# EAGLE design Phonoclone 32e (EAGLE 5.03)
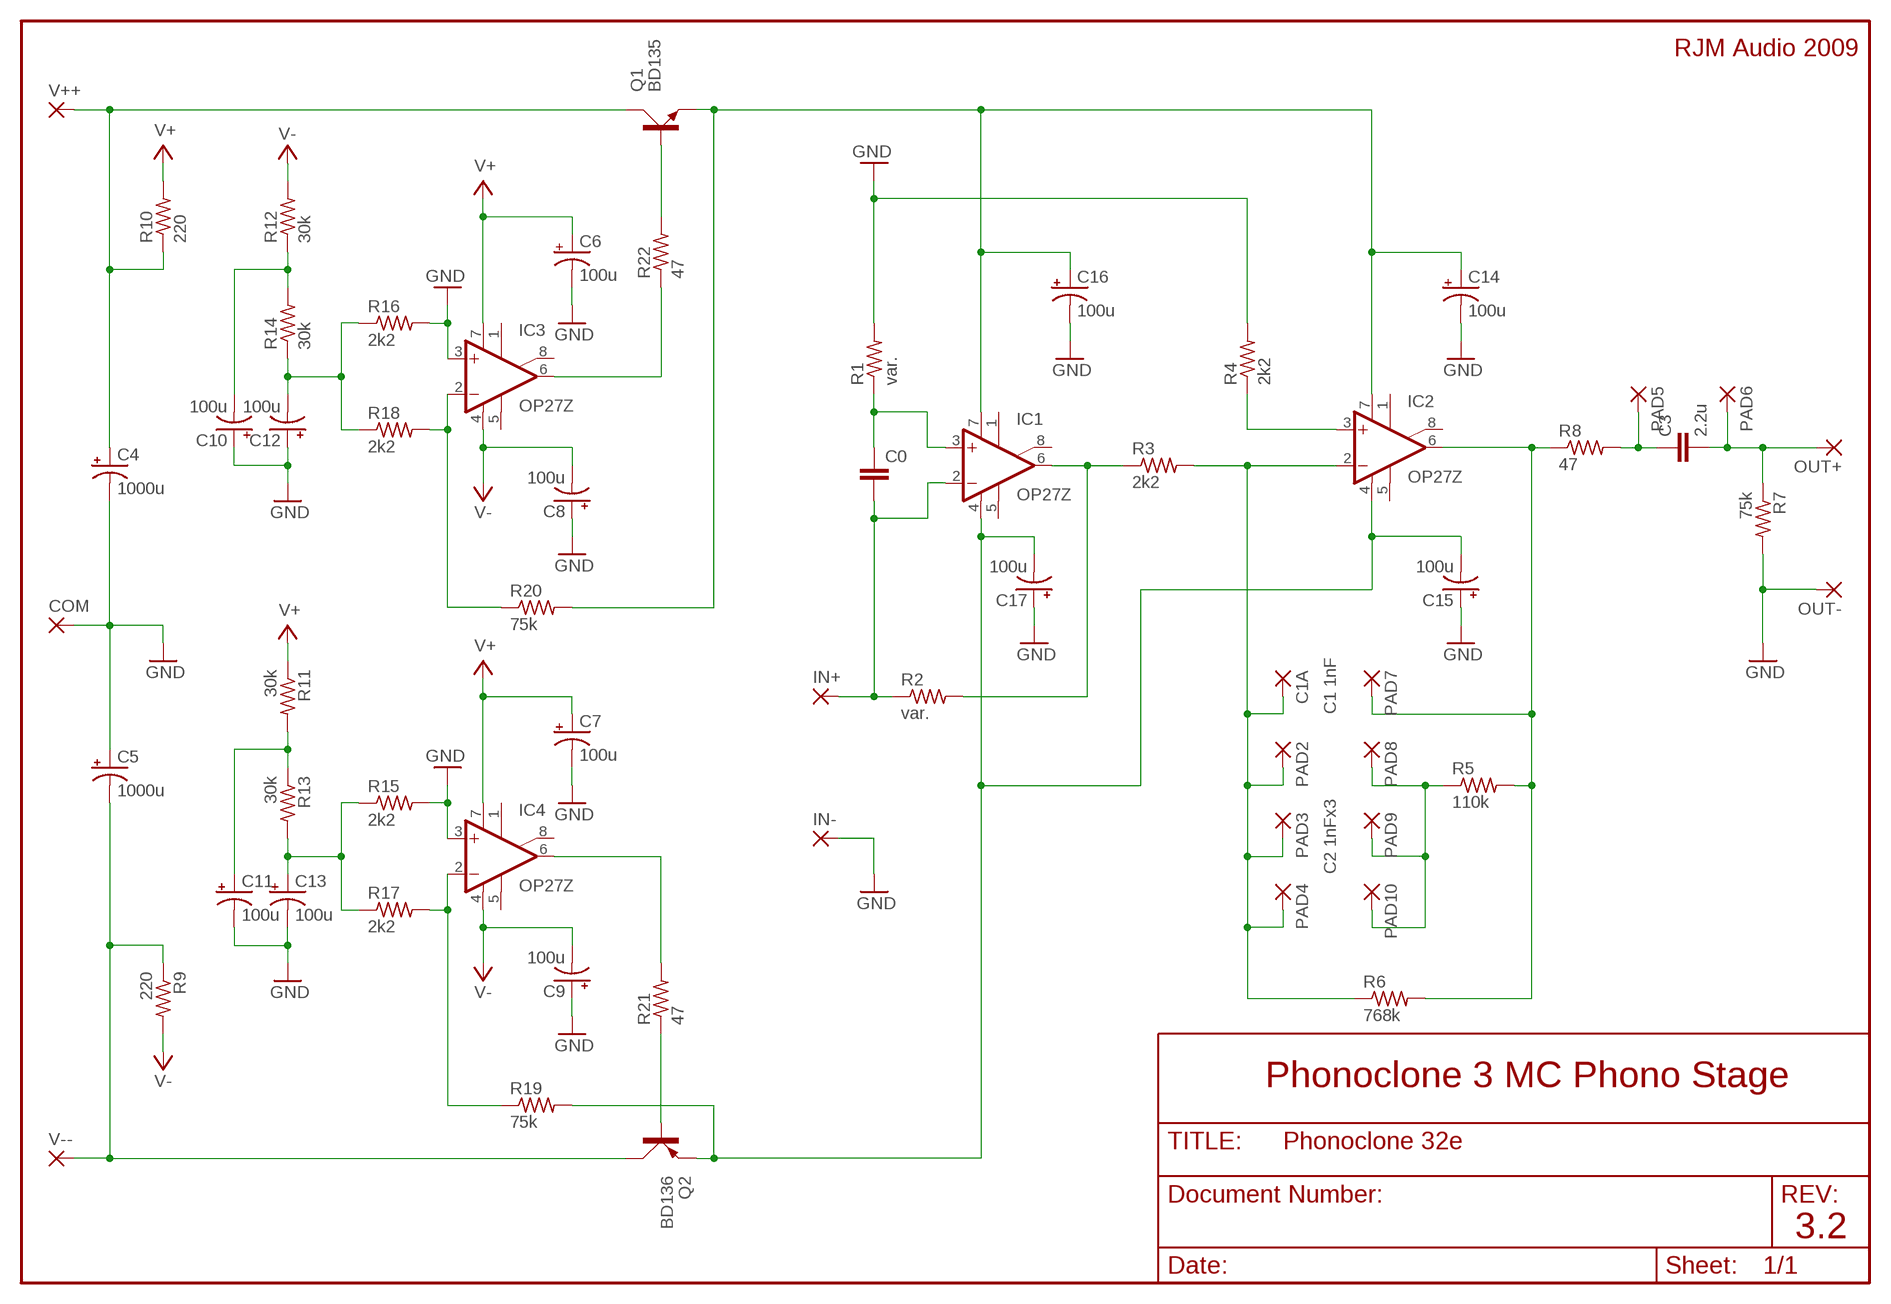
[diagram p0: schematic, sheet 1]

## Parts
C0  C-EU025-025X050  [C025-025X050]
C1A  2,54/1,1  [2,54/1,1]
C3  2.2u  C2.5/5  [C2.5-5]
C4  1000u  CPOL-USE5-10.5  [E5-10,5]
C5  1000u  CPOL-USE5-10.5  [E5-10,5]
C6  100u  CPOL-USE2.5-6  [E2,5-6]
C7  100u  CPOL-USE2.5-6  [E2,5-6]
C8  100u  CPOL-USE2.5-6  [E2,5-6]
C9  100u  CPOL-USE2.5-6  [E2,5-6]
C10  100u  CPOL-USE2.5-6  [E2,5-6]
C11  100u  CPOL-USE2.5-6  [E2,5-6]
C12  100u  CPOL-USE2.5-6  [E2,5-6]
C13  100u  CPOL-USE2.5-6  [E2,5-6]
C14  100u  CPOL-USE2.5-6  [E2,5-6]
C15  100u  CPOL-USE2.5-6  [E2,5-6]
C16  100u  CPOL-USE2.5-6  [E2,5-6]
C17  100u  CPOL-USE2.5-6  [E2,5-6]
COM  3,17/1,3  [3,17/1,3]
IC1  OP27Z  [DIL08]
IC2  OP27Z  [DIL08]
IC3  OP27Z  [DIL08]
IC4  OP27Z  [DIL08]
IN+  2,54/1,1  [2,54/1,1]
IN-  2,54/1,1  [2,54/1,1]
OUT+  2,54/1,1  [2,54/1,1]
OUT-  2,54/1,1  [2,54/1,1]
PAD2  2,54/1,1  [2,54/1,1]
PAD3  2,54/1,1  [2,54/1,1]
PAD4  2,54/1,1  [2,54/1,1]
PAD5  2,54/1,1  [2,54/1,1]
PAD6  2,54/1,1  [2,54/1,1]
PAD7  2,54/1,1  [2,54/1,1]
PAD8  2,54/1,1  [2,54/1,1]
PAD9  2,54/1,1  [2,54/1,1]
PAD10  2,54/1,1  [2,54/1,1]
Q1  BD135  BD139  [TO126AV]
Q2  BD136  BD140  [TO126AV]
R1  var.  R-US_0207/12  [0207/12]
R2  var.  R-US_0207/10  [0207/10]
R3  2k2  R-US_0207/10  [0207/10]
R4  2k2  R-US_0207/12  [0207/12]
R5  110k  R-US_0207/12  [0207/12]
R6  768k  R-US_0207/10  [0207/10]
R7  75k  R-US_0207/12  [0207/12]
R8  47  R-US_0207/12  [0207/12]
R9  220  R-US_0207/10  [0207/10]
R10  220  R-US_0207/10  [0207/10]
R11  30k  R-US_0207/10  [0207/10]
R12  30k  R-US_0207/10  [0207/10]
R13  30k  R-US_0207/10  [0207/10]
R14  30k  R-US_0207/10  [0207/10]
R15  2k2  R-US_0207/10  [0207/10]
R16  2k2  R-US_0207/10  [0207/10]
R17  2k2  R-US_0207/10  [0207/10]
R18  2k2  R-US_0207/10  [0207/10]
R19  75k  R-US_0207/10  [0207/10]
R20  75k  R-US_0207/10  [0207/10]
R21  47  R-US_0207/10  [0207/10]
R22  47  R-US_0207/10  [0207/10]
V++  3,17/1,3  [3,17/1,3]
V--  3,17/1,3  [3,17/1,3]

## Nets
GND: C4.- C5.+ C6.- C7.- C8.+ C9.+ C10.+ C11.- C12.+ C13.- C14.- C15.+ C16.- C17.+ COM.1(P) IC3.3(+IN) IC4.3(+IN) IN-.1(P) OUT-.1(P) R1.2 R4.2 R7.2 R15.2 R16.2
IN: C0.2 IC1.2(-IN) IN+.1(P) R2.1
N$2: C3.1 PAD5.1(P) R8.2
N$4: C11.+ R11.2 R13.1
N$6: IC3.6(OUT) R22.1
N$7: Q1.B R22.2
N$8: C0.1 IC1.3(+IN) R1.1
N$9: IC4.2(-IN) R17.2 R19.1
N$10: Q2.B R21.1
N$11: IC4.6(OUT) R21.2
N$13: IC3.2(-IN) R18.2 R20.1
N$14: C10.- R12.1 R14.2
OUT: IC1.6(OUT) R2.2 R3.1
OUT1: IC2.6(OUT) PAD7.1(P) R5.2 R6.2 R8.1
OUT2: C3.2 OUT+.1(P) PAD6.1(P) R7.1
P2+: IC2.3(+IN) R4.1
RIAA1: C1A.1(P) IC2.2(-IN) PAD2.1(P) PAD3.1(P) PAD4.1(P) R3.2 R6.1
RIAA2: PAD8.1(P) PAD9.1(P) PAD10.1(P) R5.1
V+: C6.+ C7.+ IC3.7(V+) IC4.7(V+) R10.2 R11.1
V++: C4.+ Q1.C R10.1 V++.1(P)
V+REG: C14.+ C16.+ IC1.7(V+) IC2.7(V+) Q1.E R20.2
V-: C8.- C9.- IC3.4(V-) IC4.4(V-) R9.2 R12.2
V--: C5.- Q2.C R9.1 V--.1(P)
V-REG: C15.- C17.- IC1.4(V-) IC2.4(V-) Q2.E R19.2
VREF+: C13.+ R13.2 R15.1 R17.1
VREF-: C12.- R14.1 R16.1 R18.1
Unconnected: IC1.1(ON1) IC1.5(OPT) IC1.8(ON2) IC2.1(ON1) IC2.5(OPT) IC2.8(ON2) IC3.1(ON1) IC3.5(OPT) IC3.8(ON2) IC4.1(ON1) IC4.5(OPT) IC4.8(ON2)

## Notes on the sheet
- RJM Audio 2009
- C1 1nF
- C2 1nFx3
- Phonoclone 3 MC Phono Stage
- 3.2

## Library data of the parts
C0 = rcl:C-EU: CAPACITOR, European symbol
C1A IN+ IN- OUT+ OUT- PAD2-PAD10 = wirepad:2,54/1,1: THROUGH-HOLE PAD
C3 = capacitor-wima:C: CAPACITOR
C4-C17 = rcl:CPOL-US: POLARIZED CAPACITOR, American symbol
COM V++ V-- = wirepad:3,17/1,3: THROUGH-HOLE PAD
IC1-IC4 = linear:OP27: OP AMP
Q1 = transistor-power:BD139: NPN TRANSISTOR
Q2 = transistor-power:BD140: PNP TRANSISTOR
R1-R22 = rcl:R-US_: RESISTOR, American symbol

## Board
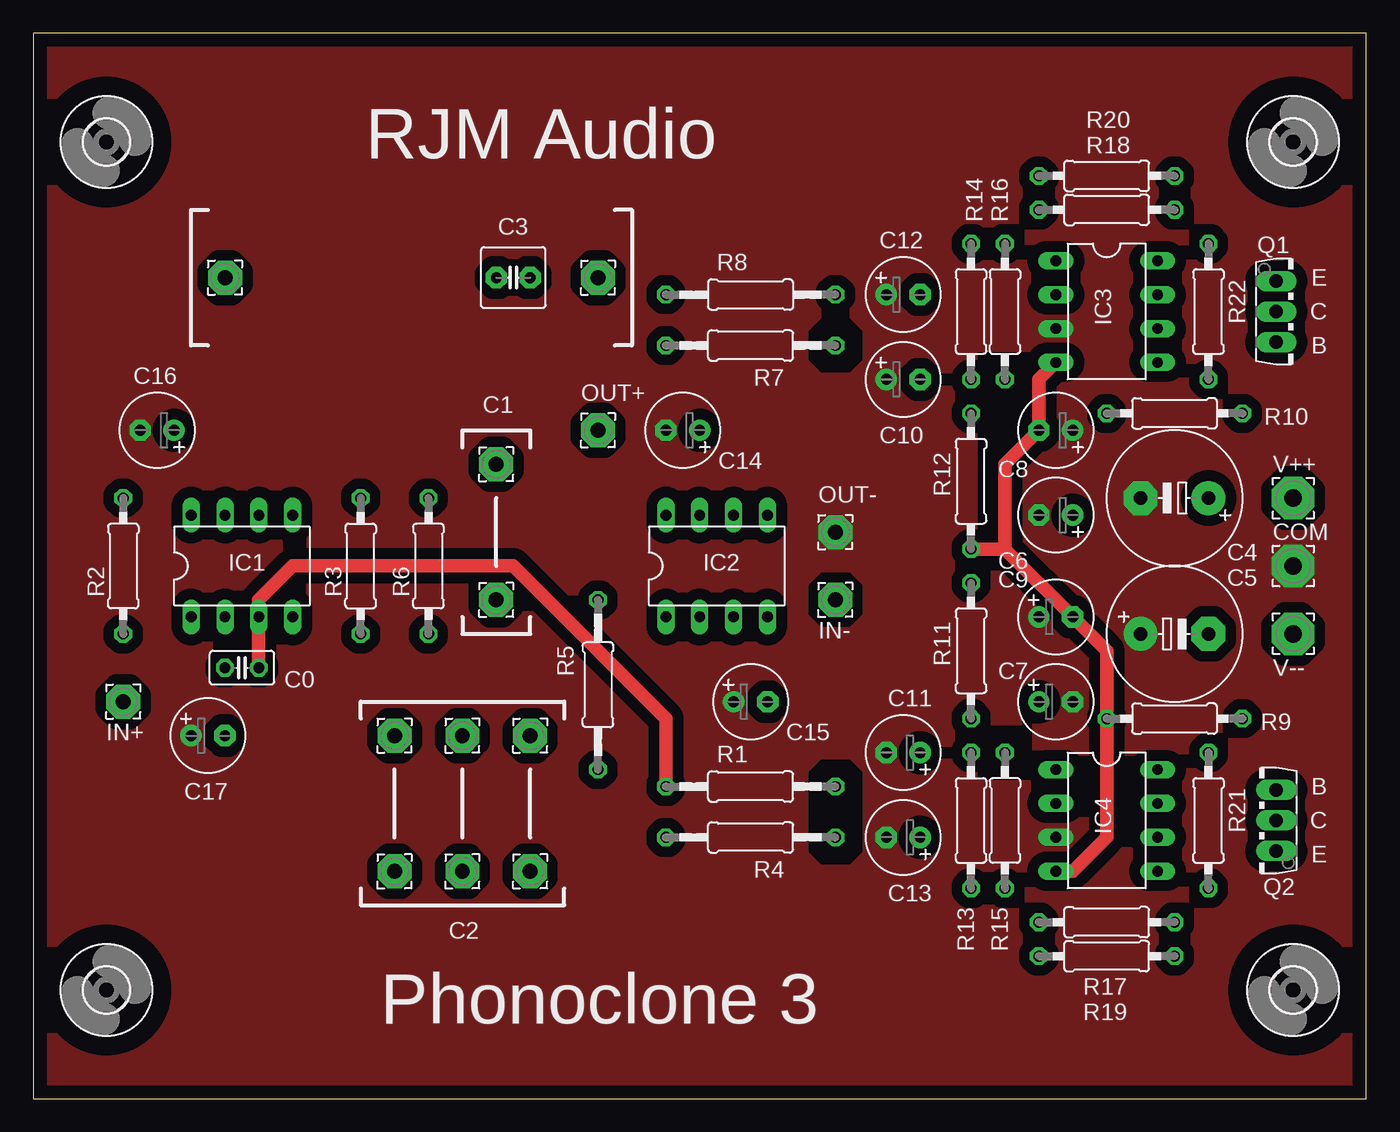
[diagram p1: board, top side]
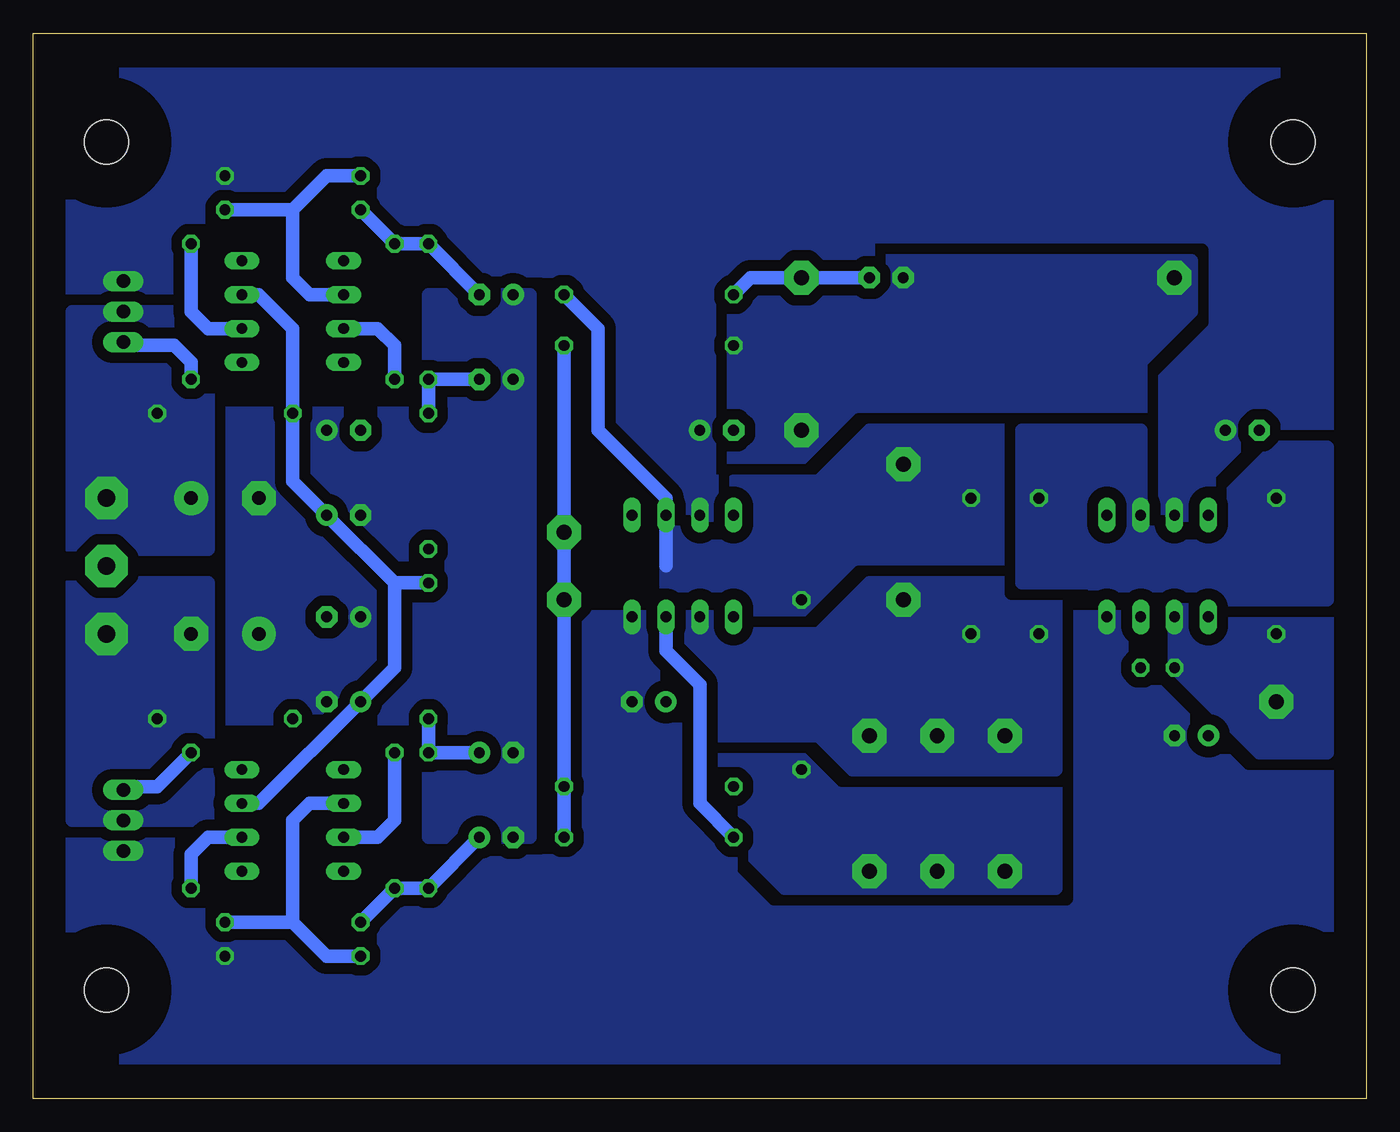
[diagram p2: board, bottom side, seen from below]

Size 99.82 x 79.76 mm. Coordinates in mm from the lower left corner, seen from the top.
Outline: 0,0 99.82,0 99.82,79.76 0,79.76 0,0
Copper layers (1*16): Top 0.035mm / dielectric 1.5mm / Bottom 0.035mm
Design rules "10mils": minimum track width 10mil, minimum drill 24mil, track to track 10mil, track to pad 10mil, pad to pad 10mil, via to via 10mil, smd to smd 10mil, copper to edge 40mil, drill to drill 10mil, minimum pad ring 10mil, minimum via ring 8mil, stop-mask expansion 0mil, vias tented up to drill 0mil, thermal gap 10mil

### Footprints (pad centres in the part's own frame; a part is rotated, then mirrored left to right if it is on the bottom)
C025-025X050 = drill 0.813 octagon: 1 -1.27,0; 2 1.27,0
2,54/1,1 = drill 1.118 pad 2.54 octagon: 1 0,0
C2.5-5 = drill 0.813 pad 1.6 octagon: 1 -1.27,0; 2 1.27,0
E5-10,5 = drill 1.016 pad 2.54 round: + -2.54,0 | drill 1.016 pad 2.54 octagon: - 2.54,0
E2,5-6 = drill 0.813 pad 1.6 round: + -1.27,0 | drill 0.813 pad 1.6 octagon: - 1.27,0
3,17/1,3 = drill 1.321 pad 3.175 octagon: 1 0,0
DIL08 = drill 0.813 long: 1 -3.81,-3.81; 2 -1.27,-3.81; 3 1.27,-3.81; 4 3.81,-3.81; 5 3.81,3.81; 6 1.27,3.81; 7 -1.27,3.81; 8 -3.81,3.81
TO126AV = drill 1.016 long: B 2.286,-1.27; C 0,-1.27; E -2.286,-1.27
0207/12 = drill 0.813 octagon: 1 -6.35,0; 2 6.35,0
0207/10 = drill 0.813 octagon: 1 -5.08,0; 2 5.08,0
3,3 = hole 3.3: 0,0

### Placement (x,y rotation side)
C0  15.62,32.26 180 top
C1A  27.05,27.18 0 top
C3  35.94,61.47 180 top
C4  85.47,44.96 180 top
C5  85.47,34.8 0 top
C6  76.58,43.69 180 top
C7  76.58,29.72 0 top
C8  76.58,50.04 180 top
C9  76.58,36.07 0 top
C10  65.15,53.85 0 top
C11  65.15,25.91 180 top
C12  65.15,60.2 0 top
C13  65.15,19.56 180 top
C14  48.64,50.04 180 top
C15  53.72,29.72 0 top
C16  9.27,50.04 180 top
C17  13.08,27.18 0 top
COM  94.36,39.88 0 top
IC1  15.62,39.88 0 top
IC2  51.18,39.88 0 top
IC3  80.39,58.93 270 top
IC4  80.39,20.83 270 top
IN+  6.73,29.72 0 top
IN-  60.07,37.34 0 top
OUT+  42.29,50.04 0 top
OUT-  60.07,42.42 0 top
PAD2  32.13,27.18 0 top
PAD3  37.21,27.18 0 top
PAD4  34.67,37.34 0 top
PAD5  42.29,61.47 0 top
PAD6  14.35,61.47 0 top
PAD7  34.67,47.5 0 top
PAD8  27.05,17.02 0 top
PAD9  32.13,17.02 0 top
PAD10  37.21,17.02 0 top
Q1  94.36,58.93 270 top
Q2  91.82,20.83 90 top
R1  53.72,23.37 0 top
R2  6.73,39.88 90 top
R3  24.51,39.88 270 top
R4  53.72,19.56 0 top
R5  42.29,30.99 90 top
R6  29.59,39.88 90 top
R7  53.72,56.39 0 top
R8  53.72,60.2 180 top
R9  85.47,28.45 180 top
R10  85.47,51.31 180 top
R11  70.23,33.53 270 top
R12  70.23,46.23 270 top
R13  70.23,20.83 270 top
R14  70.23,58.93 270 top
R15  72.77,20.83 90 top
R16  72.77,58.93 270 top
R17  80.39,13.21 0 top
R18  80.39,66.55 0 top
R19  80.39,10.67 0 top
R20  80.39,69.09 0 top
R21  88.01,20.83 270 top
R22  88.01,58.93 270 top
U$1  [3,3]  5.46,71.63 0 top
U$2  [3,3]  94.36,71.63 0 top
U$3  [3,3]  94.36,8.13 0 top
U$4  [3,3]  5.46,8.13 0 top
V++  94.36,44.96 0 top
V--  94.36,34.8 0 top

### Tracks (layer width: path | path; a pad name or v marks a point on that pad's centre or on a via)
GND
  Bottom 1.016: R7.2 OUT-.1 IN-.1 R1.2 R4.2 | R16.2 72.77,56.39 74.04,57.66 IC3.3 | R15.2 72.77,20.83 74.04,19.56 IC4.3
  pour Top (isolate 0.813, no thermals): 0.38,0.51 0.38,79.25 57.53,79.25 57.53,0.51
  pour Top (isolate 0.813, no thermals): 57.53,79.25 70.23,79.25 70.23,0.51 57.53,0.51 57.53,18.29 58.8,17.02 61.34,17.02 62.61,18.29 62.61,24.64 61.34,25.91 58.8,25.91 57.53,24.64 57.53,36.07 58.8,34.8 61.34,34.8 62.61,36.07 62.61,38.61 61.34,39.88 58.8,39.88 57.53,38.61 57.53,55.12 58.8,53.85 61.34,53.85 62.61,55.12 62.61,57.66 61.34,58.93 58.8,58.93 57.53,57.66
  pour Top (isolate 0.813, no thermals): 70.23,79.25 99.44,79.25 99.44,0.51 70.23,0.51 70.23,23.37 75.31,23.37 75.31,28.45 70.23,28.45 70.23,51.31 75.31,51.31 75.31,56.39 70.23,56.39
  pour Bottom (isolate 0.813, rank 5, no thermals): 62.61,51.31 62.61,28.45 88.01,28.45 88.01,51.31
  pour Bottom (isolate 0.813, rank 5, no thermals): 62.61,28.45 70.23,28.45 70.23,19.56 62.61,19.56
  pour Bottom (isolate 0.813, rank 5, no thermals): 62.61,51.31 62.61,60.2 70.23,60.2 70.23,51.31
IN
  pour Bottom (isolate 0.813, rank 4, no thermals): 2.92,38.61 14.35,38.61 14.35,32.26 8,25.91 2.92,25.91
N$2
  Bottom 1.016: R8.2 46.1,61.47 PAD5.1 C3.1
N$4
  Bottom 1.016: C11.+ R13.1 R11.2
N$6
  Bottom 1.016: IC3.6 86.74,57.66 88.01,58.93 R22.1
N$7
  Bottom 1.016: R22.2 88.01,55.12 89.28,56.39 92.84,56.39 Q1.B
N$8
  Top 1.016: R1.1 47.37,28.45 35.94,39.88 19.43,39.88 16.89,37.34 IC1.3 C0.1
N$9
  Bottom 1.016: IC4.2 79.12,22.1 80.39,20.83 80.39,13.21 | R19.1 77.85,10.67 80.39,13.21 | 80.39,13.21 R17.2
N$10
  Bottom 1.016: R21.1 90.55,23.37 92.84,23.37 Q2.B
N$11
  Bottom 1.016: IC4.6 86.74,19.56 88.01,18.29 R21.2
N$13
  Bottom 1.016: IC3.2 79.12,60.2 80.39,61.47 80.39,66.55 | 80.39,66.55 R18.2 | 80.39,66.55 77.85,69.09 R20.1
N$14
  Bottom 1.016: C10.- R14.2 R12.1
OUT
  pour Bottom (isolate 0.813, rank 2, no thermals): 2.92,48.77 6.73,48.77 13.08,42.42 16.89,42.42 16.89,50.04 25.78,50.04 25.78,38.61 20.7,38.61 19.43,37.34 2.92,37.34
OUT1
  Bottom 1.016: 52.45,39.88 IC2.6 52.45,44.96 57.53,50.04 57.53,57.66 R8.1
  pour Bottom (isolate 0.813, rank 4, no thermals): 25.78,34.8 52.45,34.8 52.45,42.42 47.37,42.42 47.37,46.23 41.02,46.23 37.21,50.04 25.78,50.04
OUT2
  pour Bottom (isolate 0.813, rank 5, no thermals): 13.08,62.74 13.08,58.93 16.89,55.12 16.89,46.23 47.37,46.23 47.37,60.2 38.48,60.2 35.94,62.74
P2+
  Bottom 1.016: R4.1 49.91,22.1 49.91,30.99 52.45,33.53 IC2.3
RIAA1
  pour Bottom (isolate 0.813, rank 3, no thermals): 23.24,38.61 23.24,24.64 38.48,24.64 41.02,27.18 49.91,27.18 49.91,30.99 51.18,32.26 51.18,36.07 48.64,36.07 48.64,34.8 41.02,34.8 37.21,38.61
RIAA2
  pour Bottom (isolate 0.813, rank 5, no thermals): 23.24,28.45 49.91,28.45 49.91,22.1 43.56,15.75 23.24,15.75
V+
  Bottom 1.016: IC3.7 82.93,60.2 80.39,57.66 R10.2 80.39,46.23 C6.+ 72.77,38.61 | IC4.7 82.93,22.1 C7.+ 72.77,32.26 72.77,38.61 | 72.77,38.61 R11.1
V++
  pour Bottom (isolate 0.813, no thermals): 86.74,41.15 96.9,41.15 96.9,58.93 86.74,58.93
V+REG
  pour Bottom (isolate 0.813, rank 6, no thermals): 2.92,43.69 2.92,76.71 96.9,76.71 96.9,43.69
V-
  Top 1.016: IC3.4 75.31,53.85 C8.- 72.77,47.5 72.77,41.15 | IC4.4 77.85,17.02 80.39,19.56 R9.2 80.39,30.99 80.39,33.53 C9.- 72.77,41.15 | 72.77,41.15 R12.2
V--
  pour Bottom (isolate 0.813, no thermals): 86.74,38.61 96.9,38.61 96.9,20.83 86.74,20.83
V-REG
  pour Bottom (isolate 0.813, rank 6, no thermals): 2.92,3.05 2.92,36.07 96.9,36.07 96.9,3.05
VREF+
  Bottom 1.016: R15.1 R17.1 R15.1 | C13.+ R13.2 R15.1
VREF-
  Bottom 1.016: R18.1 R16.1 R14.1 C12.-

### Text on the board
tPlace: RJM Audio | Phonoclone 3
tNames: E | C | B | C1 | B | C | E | C2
